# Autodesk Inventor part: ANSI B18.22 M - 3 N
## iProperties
Comments: To add or edit properties for Autodesk Inventor files, use iProperties.
Created: 2004-08
Part Number: ANSI B18.22 M - 3 N
Vendor: Autodesk Inc.
Document SubType Name: Modeling
Designer: John Blackburn
Material: Default
Description: Plain Washer
Standard: ANSI B18.22 M
Size Designation: 3 N
Alert: To add or edit properties for Autodesk Inventor files, use iProperties.
Control State: 0
Master: False
Checked Out: False
Shininess: 64.0
Length Units: 11269
Angle Units: 11279
Time Units: 11290
Mass Units: 11283
Length Display Precision: 3
Angle Display Precision: 2
Compacted: True
Classification: un/spsc 31161807
Density: 0.0
Volumn: 0.0
Area: 0.0
PropertySet Name: Model Information
Author: John Blackburn
Revision Number: 8
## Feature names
1. Body [Extrusion]
